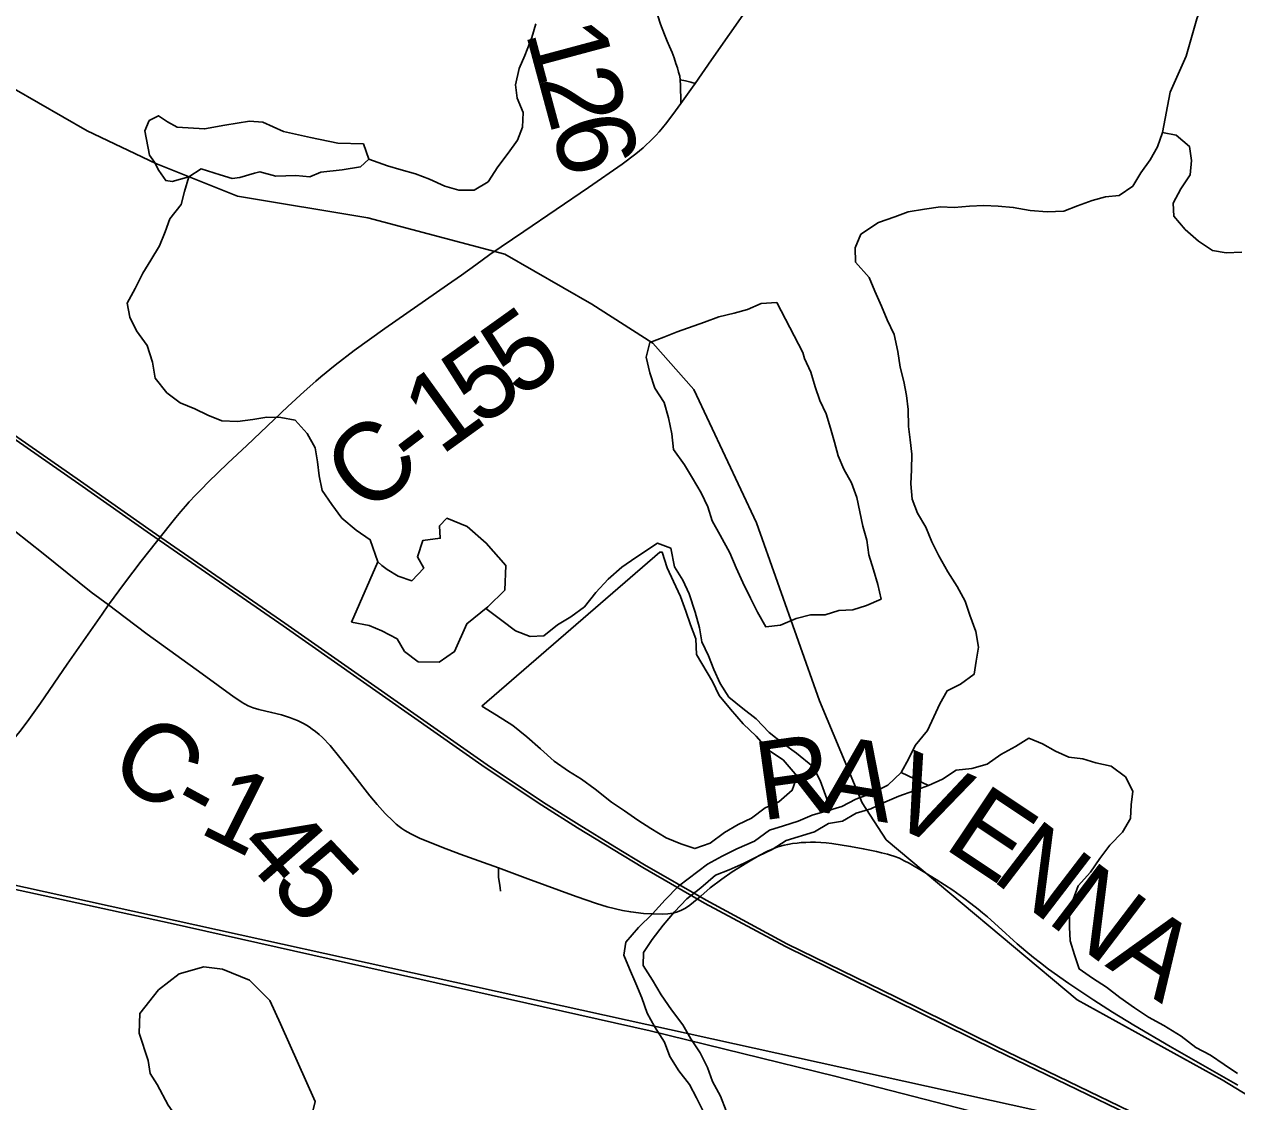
# Model space of a CAD drawing. Extents: x 0 to 34, y 0 to 22.
# Drawn here: x 2.727 to 3.606, y 15.546 to 16.327 of the extents above; entities that cross this region are included whole.
import ezdxf

# ---------------------------------------------------------------- set-up
doc = ezdxf.new("R2010")
doc.units = 0
for name, color, linetype in [('GM_X_County_Road', 7, 'Continuous'), ('GM_X_County_Road_Text', 7, 'Continuous'), ('GM_X_Major_Lake', 7, 'Continuous'), ('GM_X_Major_River', 7, 'Continuous'), ('GM_X_Minor_Lake', 7, 'Continuous'), ('GM_X_Minor_River', 7, 'Continuous'), ('GM_X_Rail_Line', 7, 'Continuous'), ('GM_X_Township_Road', 7, 'Continuous'), ('GM_X_Township_Road_Text', 7, 'Continuous')]:
    doc.layers.add(name, color=color, linetype=linetype)

msp = doc.modelspace()

# ---------------------------------------------------------------- linework, layer by layer
at = {"layer": 'GM_X_County_Road'}
for points in [[(3.21325, 16.2844), (3.22511, 16.30148), (3.25115, 16.33858), (3.26321, 16.35568), (3.28202, 16.38267), (3.2934, 16.39887), (3.29907, 16.407), (3.30365, 16.41331)], [(3.20286, 16.26972), (3.21128, 16.28158), (3.21325, 16.2844)], [(2.93829, 16.0684), (2.9421, 16.07173), (2.95225, 16.07998), (2.96608, 16.0906), (2.98827, 16.10666), (3.03365, 16.13823), (3.04381, 16.14533), (3.0543, 16.15285), (3.06436, 16.16019), (3.08899, 16.17707), (3.13581, 16.20881), (3.16029, 16.2258), (3.17019, 16.23325), (3.17279, 16.23541), (3.17541, 16.2376), (3.17796, 16.23998), (3.18022, 16.24209), (3.1826, 16.24432), (3.185, 16.24689), (3.18722, 16.24927), (3.18963, 16.25219), (3.19273, 16.25593), (3.19905, 16.26435), (3.20286, 16.26972)], [(2.7881, 15.9062), (2.7997, 15.92203), (2.81187, 15.93795), (2.83306, 15.96475), (2.837, 15.9696), (2.8405, 15.97392), (2.84392, 15.97782), (2.84664, 15.98092), (2.85129, 15.98593), (2.85551, 15.99022), (2.86045, 15.99522), (2.87469, 16.00908), (2.88827, 16.02182), (2.91799, 16.05011), (2.92989, 16.06108), (2.93829, 16.0684)], [(2.5626, 16.05258), (2.57121, 16.05117), (2.57823, 16.04978), (2.58483, 16.04827), (2.58905, 16.04721), (2.59256, 16.04611), (2.5963, 16.04484), (2.60016, 16.04353), (2.60388, 16.04202), (2.60805, 16.0403), (2.6124, 16.03832), (2.61713, 16.03607), (2.61994, 16.03456), (2.62308, 16.03283), (2.62784, 16.02998), (2.63141, 16.02762), (2.63558, 16.02488), (2.64168, 16.02054), (2.6476, 16.01612), (2.68054, 15.99068), (2.70942, 15.96809), (2.74069, 15.94354), (2.7756, 15.91558), (2.7881, 15.9062)], [(2.59574, 15.75929), (2.60092, 15.76069), (2.60585, 15.76228), (2.64217, 15.775), (2.68627, 15.78944), (2.6896, 15.79061), (2.69271, 15.79169), (2.69623, 15.79318), (2.69901, 15.79436), (2.70174, 15.7957), (2.70347, 15.79655), (2.7067, 15.79841), (2.70879, 15.79988), (2.71077, 15.80126), (2.71289, 15.80306), (2.71503, 15.80487), (2.71727, 15.80709), (2.71944, 15.80926), (2.72388, 15.81445), (2.72912, 15.82141), (2.73885, 15.83508), (2.75828, 15.8632), (2.78361, 15.89954), (2.7881, 15.9062)], [(2.7881, 15.9062), (2.8001, 15.89713), (2.81604, 15.88512), (2.83693, 15.87004), (2.85604, 15.85618), (2.87916, 15.83933), (2.88256, 15.83709), (2.88494, 15.83553), (2.88673, 15.83458), (2.88941, 15.83316), (2.89295, 15.83175), (2.89716, 15.83046), (2.90628, 15.82833), (2.91348, 15.82655), (2.91993, 15.8245), (2.92249, 15.82346), (2.92505, 15.82243), (2.92944, 15.82029), (2.93153, 15.81904), (2.93363, 15.81779), (2.93582, 15.81621), (2.93809, 15.81457), (2.94074, 15.81222), (2.94314, 15.81009), (2.94865, 15.80428), (2.95583, 15.79574), (2.96504, 15.78408), (2.97753, 15.7678), (2.98271, 15.76155), (2.98862, 15.7551), (2.9944, 15.74936), (2.99653, 15.74733), (2.99867, 15.74563), (3.00065, 15.7441), (3.0028, 15.7427), (3.005, 15.74143), (3.00717, 15.74018), (3.01048, 15.73853), (3.0134, 15.73721), (3.02953, 15.73056), (3.04291, 15.72546), (3.0564, 15.72072), (3.07061, 15.71555)], [(3.07061, 15.71555), (3.09202, 15.70775), (3.127, 15.69481), (3.14175, 15.68975), (3.14952, 15.68743), (3.16063, 15.68481), (3.16648, 15.68363), (3.17584, 15.68249), (3.18922, 15.68208), (3.19345, 15.6824), (3.19728, 15.68284), (3.20041, 15.68363), (3.20339, 15.68484), (3.20618, 15.68642), (3.20927, 15.68865), (3.21737, 15.69514), (3.22402, 15.70106), (3.23249, 15.70732), (3.2401, 15.71262), (3.25057, 15.71926), (3.25963, 15.72459), (3.26566, 15.72767), (3.27301, 15.73079), (3.27772, 15.73206), (3.28028, 15.73256), (3.28374, 15.73322), (3.28706, 15.7336), (3.28988, 15.73393), (3.29326, 15.73407), (3.29671, 15.73422), (3.30036, 15.73413), (3.30421, 15.73403), (3.30811, 15.73369), (3.31231, 15.73331), (3.32578, 15.73115), (3.33495, 15.72947), (3.34466, 15.72745), (3.34826, 15.72659), (3.35247, 15.72559), (3.35477, 15.72489), (3.35715, 15.72416), (3.36112, 15.7226), (3.36461, 15.72081), (3.36824, 15.71894), (3.3784, 15.71305), (3.38789, 15.70713), (3.39986, 15.69935), (3.40795, 15.69364), (3.41298, 15.68976), (3.41823, 15.68572), (3.42148, 15.68302), (3.42489, 15.68018), (3.43271, 15.67313), (3.44654, 15.66065), (3.45287, 15.6553), (3.4584, 15.6506), (3.46334, 15.64683), (3.46928, 15.64229), (3.48392, 15.63175), (3.50203, 15.61966), (3.51566, 15.61093), (3.53107, 15.60155), (3.55728, 15.586), (3.60646, 15.55803)]]:
    msp.add_lwpolyline(points, dxfattribs=at)
at = {"layer": 'GM_X_Major_Lake'}
msp.add_line((3.36247, 15.78464), (3.38221, 15.77531), dxfattribs=at)
msp.add_line((3.36247, 15.78464), (3.38221, 15.77531), dxfattribs=at)
for points in [[(3.60931, 16.16196), (3.59796, 16.16149), (3.5881, 16.16331), (3.57783, 16.17006), (3.5683, 16.17832), (3.5599, 16.18812), (3.55945, 16.19759), (3.56504, 16.20787), (3.57177, 16.21817), (3.57283, 16.22841), (3.57124, 16.23864), (3.56171, 16.24691), (3.55185, 16.24872), (3.54815, 16.23846), (3.54293, 16.22894), (3.53619, 16.21941), (3.53021, 16.20988), (3.52042, 16.20298), (3.51059, 16.20214), (3.50077, 16.19941), (3.4902, 16.19554), (3.48039, 16.19167), (3.46828, 16.1912), (3.45579, 16.19224), (3.44366, 16.19442), (3.43267, 16.19547), (3.42245, 16.19577), (3.41186, 16.19531), (3.40089, 16.19447), (3.39105, 16.19477), (3.37933, 16.19316), (3.36761, 16.19118), (3.3578, 16.18769), (3.3461, 16.18343), (3.3333, 16.17499), (3.32921, 16.1651), (3.32929, 16.15486), (3.33922, 16.14356), (3.34346, 16.13373), (3.34809, 16.12278), (3.35233, 16.11295), (3.35733, 16.10237), (3.36008, 16.08988), (3.36168, 16.07851), (3.36441, 16.0683), (3.36638, 16.05807), (3.3676, 16.04785), (3.36769, 16.03571), (3.3689, 16.02586), (3.37012, 16.01564), (3.36983, 16.00426), (3.36953, 15.99402), (3.37038, 15.98303), (3.37424, 15.97282), (3.38038, 15.96263), (3.38462, 15.95204), (3.38962, 15.94184), (3.39615, 15.93014), (3.40305, 15.91957), (3.40881, 15.909), (3.41229, 15.89879), (3.41655, 15.88707), (3.41853, 15.87571), (3.41672, 15.86545), (3.41528, 15.85596), (3.40549, 15.84868), (3.39569, 15.84406), (3.39047, 15.83454), (3.386, 15.82502), (3.38154, 15.81513), (3.37254, 15.80444), (3.36807, 15.79493), (3.36247, 15.78464)], [(3.38221, 15.77531), (3.39241, 15.77995), (3.4022, 15.78647), (3.41354, 15.78769), (3.42487, 15.79082), (3.43466, 15.79772), (3.44521, 15.80349), (3.455, 15.80963), (3.46487, 15.80553), (3.47438, 15.8003), (3.48387, 15.79582), (3.4941, 15.79476), (3.50359, 15.7918)], [(3.50359, 15.7918), (3.51458, 15.78923), (3.52486, 15.78173), (3.53024, 15.77115), (3.52919, 15.76129), (3.52851, 15.75142), (3.5229, 15.74152), (3.51352, 15.73197), (3.5064, 15.72243), (3.49967, 15.71252), (3.49066, 15.70259), (3.48695, 15.6927), (3.48439, 15.68244), (3.48446, 15.67258), (3.48492, 15.66273), (3.48802, 15.65251), (3.49151, 15.6423), (3.50103, 15.63555), (3.5113, 15.62918), (3.52082, 15.62167), (3.53147, 15.61417), (3.54174, 15.60742), (3.55277, 15.60144), (3.56532, 15.59357), (3.57598, 15.58532), (3.58662, 15.57971), (3.59651, 15.57296), (3.60602, 15.56659)]]:
    msp.add_lwpolyline(points, dxfattribs=at)
at = {"layer": 'GM_X_Major_River'}
msp.add_line((3.38221, 15.77531), (3.36247, 15.78464), dxfattribs=at)
msp.add_line((3.38221, 15.77531), (3.36247, 15.78464), dxfattribs=at)
for points in [[(3.36247, 15.78464), (3.3527, 15.77547)], [(3.3527, 15.77547), (3.3414, 15.76969), (3.32969, 15.76543), (3.31952, 15.76004), (3.30894, 15.75693), (3.29799, 15.75381), (3.28781, 15.74956), (3.27724, 15.74607), (3.26705, 15.74296), (3.25613, 15.73491), (3.2433, 15.7295), (3.23275, 15.72411), (3.2222, 15.71834), (3.20113, 15.70225), (3.19137, 15.69232), (3.18236, 15.68239), (3.17222, 15.67245), (3.16284, 15.66176), (3.1614, 15.65227), (3.16564, 15.64244), (3.17027, 15.63186), (3.17451, 15.62127), (3.17838, 15.61031), (3.18376, 15.60049), (3.19104, 15.58917), (3.1949, 15.57896), (3.20142, 15.56839), (3.20907, 15.55859), (3.21406, 15.54877), (3.21983, 15.53782)], [(3.23571, 15.53946), (3.23146, 15.55004), (3.2257, 15.56061), (3.22222, 15.57083), (3.21684, 15.5814), (3.20994, 15.59159), (3.20419, 15.60178), (3.19615, 15.61272), (3.1885, 15.62365), (3.18236, 15.63423), (3.17547, 15.64479), (3.17577, 15.65427), (3.18213, 15.6638), (3.19, 15.6741), (3.19825, 15.68365), (3.20726, 15.6932), (3.21741, 15.70124), (3.22794, 15.71042), (3.23775, 15.71429), (3.24869, 15.71892), (3.25924, 15.72431), (3.26905, 15.72894), (3.27921, 15.73546), (3.2996, 15.74169), (3.30977, 15.74783), (3.31998, 15.74943), (3.32978, 15.75519), (3.34035, 15.75831), (3.35053, 15.76332), (3.36071, 15.76757), (3.37166, 15.77144), (3.38221, 15.77531)]]:
    msp.add_lwpolyline(points, dxfattribs=at)
at = {"layer": 'GM_X_Minor_Lake'}
for p, q in [((2.89769, 16.22015), (2.90945, 16.21721)), ((3.2912, 16.08935), (3.27237, 16.1256)), ((2.98318, 15.93757), (2.96422, 15.89381)), ((3.1875, 15.94445), (3.05856, 15.83273)), ((2.81842, 15.56658), (2.8234, 15.55865))]:
    msp.add_line(p, q, dxfattribs=at)
for points in [[(2.90945, 16.21721), (2.92383, 16.2177), (2.93405, 16.21664), (2.94197, 16.22012), (2.95748, 16.22175), (2.97071, 16.22375), (2.97672, 16.22949), (2.97285, 16.24045), (2.9543, 16.24107), (2.93459, 16.24509), (2.91487, 16.24948), (2.90006, 16.2562), (2.89021, 16.25688), (2.87244, 16.25409), (2.85771, 16.25132), (2.83801, 16.25268), (2.8308, 16.25642), (2.82432, 16.26092), (2.81754, 16.25745), (2.81457, 16.24985), (2.81774, 16.23243), (2.82156, 16.22715), (2.82464, 16.22111), (2.82962, 16.21394), (2.83416, 16.21322), (2.84625, 16.21672), (2.85528, 16.22248), (2.86894, 16.21804), (2.87767, 16.21545), (2.88334, 16.21625), (2.89391, 16.21937), (2.89769, 16.22015)], [(3.27237, 16.1256), (3.26102, 16.12476), (3.25121, 16.12051), (3.2414, 16.11778), (3.23044, 16.11504), (3.21987, 16.11117), (3.20025, 16.10419), (3.19044, 16.10032), (3.18025, 16.09645), (3.17768, 16.08581), (3.18042, 16.07446), (3.18391, 16.06349), (3.19081, 16.05293), (3.19392, 16.04195), (3.19629, 16.03022), (3.19751, 16.01885), (3.20555, 16.00792), (3.2113, 15.9981), (3.21744, 15.98753), (3.22244, 15.97733), (3.22555, 15.96712), (3.2313, 15.95693), (3.23822, 15.94408), (3.24284, 15.93312), (3.24785, 15.92254), (3.25323, 15.91121), (3.25824, 15.90101), (3.26437, 15.89044), (3.27496, 15.89166), (3.28628, 15.8963), (3.29686, 15.89904), (3.30745, 15.89912), (3.31727, 15.90222), (3.32748, 15.90268), (3.3373, 15.90579), (3.34786, 15.91043), (3.34551, 15.92102), (3.3424, 15.93162), (3.3389, 15.94259), (3.33768, 15.9532), (3.33458, 15.96341), (3.3326, 15.97363), (3.33025, 15.98423), (3.32638, 15.99482), (3.32101, 16.00464), (3.31676, 16.01446), (3.31404, 16.0243), (3.31131, 16.03452), (3.3082, 16.04473), (3.30358, 16.05455), (3.3001, 16.06439), (3.29699, 16.07498), (3.29237, 16.0848), (3.2912, 16.08935)], [(2.96422, 15.89381), (2.9771, 15.89126), (2.98622, 15.88754), (2.99724, 15.88155), (3.00261, 15.8725), (3.01251, 15.86499), (3.02765, 15.86473), (3.03894, 15.8724), (3.04787, 15.89256), (3.06291, 15.90481), (3.07531, 15.91704), (3.07592, 15.93487), (3.06179, 15.95107), (3.04807, 15.96309), (3.03326, 15.96905), (3.02801, 15.9637), (3.02846, 15.9546), (3.01598, 15.95299), (3.01191, 15.9412), (3.01652, 15.93289), (3.00788, 15.92373), (2.99802, 15.92706), (2.99003, 15.93193), (2.98622, 15.93493), (2.98318, 15.93757)], [(3.05856, 15.83273), (3.06921, 15.82637), (3.081, 15.81887), (3.09128, 15.81061), (3.10119, 15.80197), (3.1111, 15.79294), (3.12137, 15.78582), (3.13088, 15.77982), (3.14078, 15.7727), (3.15258, 15.76331), (3.1621, 15.75693), (3.17161, 15.75018), (3.18112, 15.74419), (3.19215, 15.73745), (3.20278, 15.73298), (3.21303, 15.72965), (3.22397, 15.73352), (3.23451, 15.74119), (3.2443, 15.74695), (3.25411, 15.75157), (3.26389, 15.75923), (3.2737, 15.76348), (3.28347, 15.7719), (3.28718, 15.78217), (3.27687, 15.79384), (3.26621, 15.80097), (3.25743, 15.81114), (3.24789, 15.82016), (3.23873, 15.83071), (3.2307, 15.84051), (3.2257, 15.85071), (3.21419, 15.87034), (3.21373, 15.88171), (3.20986, 15.89192), (3.20638, 15.90175), (3.20251, 15.91234), (3.1975, 15.92329), (3.19289, 15.93312), (3.18939, 15.94447), (3.1875, 15.94445)], [(2.8234, 15.55865), (2.83147, 15.54355), (2.8418, 15.52884), (2.85248, 15.51792), (2.86734, 15.50552), (2.87984, 15.5041), (2.8991, 15.51032), (2.91538, 15.50893), (2.9312, 15.51891), (2.9378, 15.54626), (2.91276, 15.60257), (2.90505, 15.61957), (2.89018, 15.63425), (2.87081, 15.64207), (2.85718, 15.64386), (2.83943, 15.63879), (2.82438, 15.6273), (2.81089, 15.61013), (2.81024, 15.59572), (2.81683, 15.57604), (2.81842, 15.56658)]]:
    msp.add_lwpolyline(points, dxfattribs=at)
at = {"layer": 'GM_X_Minor_River'}
for points in [[(3.55185, 16.24872), (3.5573, 16.27797), (3.56883, 16.30422), (3.57657, 16.3312), (3.58954, 16.36619), (3.59464, 16.39163), (3.59412, 16.40869), (3.59174, 16.42308), (3.59202, 16.4356)], [(2.97672, 16.22949), (2.99038, 16.22466), (3.00025, 16.2217), (3.01049, 16.21875), (3.02074, 16.21504), (3.03175, 16.20981), (3.042, 16.20686), (3.05297, 16.20695), (3.06314, 16.21309), (3.07025, 16.22376), (3.07774, 16.23368), (3.08448, 16.24321), (3.08819, 16.25272), (3.08848, 16.26334), (3.08424, 16.27354), (3.08303, 16.28339), (3.08558, 16.29517), (3.08967, 16.30468), (3.09487, 16.31761), (3.09782, 16.32749)], [(2.98318, 15.93757), (2.97775, 15.95345), (2.96748, 15.96057), (2.95719, 15.96922), (2.94992, 15.97902), (2.94303, 15.9892), (2.94068, 15.9998), (2.93946, 16.01003), (2.93787, 16.02026), (2.93211, 16.03045), (2.92333, 16.04024), (2.91309, 16.04206), (2.90287, 16.04236), (2.89267, 16.04076), (2.8817, 16.03916), (2.87034, 16.03983), (2.86009, 16.04393), (2.8506, 16.0484), (2.83996, 16.05287), (2.83044, 16.06), (2.82204, 16.07055), (2.82005, 16.08229), (2.81617, 16.0944), (2.80852, 16.10496), (2.80352, 16.11478), (2.80155, 16.125), (2.80752, 16.13566), (2.81311, 16.1467), (2.81871, 16.15622), (2.82507, 16.16651), (2.82915, 16.17678), (2.83248, 16.18628), (2.84073, 16.19658), (2.8433, 16.20608), (2.84625, 16.21672)], [(3.31148, 15.75768), (3.30772, 15.7683), (3.30385, 15.77888), (3.29847, 15.78908), (3.28666, 15.79885), (3.27715, 15.8056), (3.26687, 15.81386), (3.25733, 15.82365), (3.24781, 15.83116), (3.23752, 15.83942), (3.23139, 15.84923), (3.22677, 15.85944), (3.22291, 15.86927), (3.21791, 15.87947), (3.21631, 15.88969), (3.2132, 15.90104), (3.20893, 15.91428), (3.20431, 15.92411), (3.19818, 15.93392), (3.19553, 15.9474), (3.1858, 15.951), (3.17012, 15.94053), (3.15995, 15.93362), (3.15018, 15.92482), (3.14118, 15.91528), (3.13293, 15.90497), (3.12315, 15.89769), (3.11335, 15.89193), (3.10357, 15.88389), (3.09374, 15.88344), (3.08311, 15.88753), (3.07321, 15.89503), (3.06152, 15.90368)]]:
    msp.add_lwpolyline(points, dxfattribs=at)
at = {"layer": 'GM_X_Rail_Line'}
for points in [[(2.11404, 16.8374), (2.11458, 16.83676), (2.1893, 16.75144), (2.2758, 16.63594), (2.32038, 16.58606), (2.38068, 16.52962), (2.50392, 16.43116), (2.61143, 16.35633), (2.70189, 16.29068), (2.7727, 16.24998), (2.82252, 16.22634), (2.88153, 16.2027), (2.97595, 16.18691), (3.07524, 16.16059), (3.13833, 16.12429), (3.18262, 16.09607), (3.21214, 16.06247), (3.25775, 15.96574), (3.30335, 15.83677), (3.3342, 15.76288), (3.35164, 15.736), (3.48992, 15.62004), (3.59498, 15.56194), (3.68719, 15.50564)], [(3.62937, 15.49013), (3.53553, 15.53548), (3.43164, 15.58576), (3.35923, 15.62155), (3.27967, 15.66062), (3.22117, 15.69212), (3.17637, 15.71789), (3.15489, 15.73098), (3.12912, 15.74673), (3.10335, 15.7631), (3.06244, 15.7903), (2.91598, 15.89299), (2.81985, 15.95946), (2.76789, 15.99587), (2.7008, 16.04271), (2.59761, 16.11492), (2.4486, 16.21924), (2.34939, 16.28837), (2.27299, 16.34186), (2.18995, 16.39965), (2.11404, 16.45303)], [(3.62833, 15.48803), (3.5345, 15.53338), (3.43061, 15.58366), (3.3582, 15.61946), (3.27859, 15.65855), (3.22002, 15.69008), (3.17517, 15.71589), (3.15367, 15.72899), (3.12788, 15.74476), (3.10207, 15.76114), (3.06111, 15.78838), (2.91464, 15.89107), (2.8185, 15.95755), (2.76655, 15.99396), (2.69946, 16.0408), (2.59626, 16.11301), (2.44725, 16.21733), (2.34805, 16.28646), (2.27165, 16.33995), (2.1886, 16.39774), (2.11404, 16.45017)], [(2.11404, 15.83803), (2.21072, 15.81673), (2.40039, 15.77358), (3.45866, 15.54025), (3.56111, 15.51059), (3.62916, 15.49068)], [(3.91685, 15.34723), (3.85553, 15.37214), (3.6811, 15.44955), (3.57506, 15.49641), (3.50847, 15.51449), (3.31447, 15.56464), (3.18048, 15.59752), (2.83277, 15.67561), (2.27379, 15.79727), (2.13158, 15.82604)]]:
    msp.add_lwpolyline(points, dxfattribs=at)
at = {"layer": 'GM_X_Township_Road'}
for points in [[(3.20235, 16.28697), (3.20198, 16.28956), (3.20119, 16.2924), (3.20035, 16.29564), (3.1993, 16.29886), (3.19795, 16.30285), (3.19651, 16.30679), (3.19459, 16.31112), (3.19296, 16.31486), (3.19103, 16.31979), (3.1881, 16.3273), (3.18453, 16.33855), (3.1804, 16.35288), (3.17722, 16.36548), (3.17635, 16.36982), (3.17548, 16.37415), (3.17461, 16.37982), (3.17372, 16.3857), (3.17279, 16.39466), (3.17109, 16.40992), (3.17066, 16.41377)], [(3.20286, 16.26972), (3.20271, 16.27344), (3.20259, 16.28031), (3.20247, 16.2829), (3.20235, 16.28697)], [(3.21325, 16.2844), (3.20997, 16.2852), (3.2063, 16.28611), (3.20235, 16.28697)], [(3.07226, 15.69869), (3.07196, 15.70115), (3.07145, 15.70446), (3.07075, 15.70873), (3.07061, 15.71064), (3.07061, 15.7126), (3.07061, 15.71555)]]:
    msp.add_lwpolyline(points, dxfattribs=at)

# ---------------------------------------------------------------- texts
at = {"layer": 'GM_X_County_Road_Text'}
for s, rotation, p in [('5', 35.61148, (3.08567, 16.05483)), ('5', 35.64475, (3.05724, 16.03444)), ('1', 35.84257, (3.02891, 16.01397)), ('C', 41.34086, (2.97641, 15.96994)), ('-', 37.19307, (3.01061, 16.00008)), ('C', 323.76631, (2.78552, 15.78596)), ('R', 7.88558, (3.26114, 15.74982)), ('A', 350.77663, (3.3029, 15.75627)), ('V', 336.56273, (3.34868, 15.7493)), ('1', 333.30751, (2.85244, 15.7418)), ('-', 331.3258, (2.83007, 15.75399)), ('E', 326.28498, (3.39219, 15.7307)), ('4', 311.42826, (2.8792, 15.72955)), ('N', 322.5589, (3.42675, 15.70768)), ('5', 313.36696, (2.90377, 15.70176)), ('N', 322.77981, (3.46664, 15.67714)), ('A', 326.28146, (3.50954, 15.6447))]:
    msp.add_text(s, height=0.05682, rotation=rotation, dxfattribs=at).set_placement(p)
at = {"layer": 'GM_X_Township_Road_Text'}
for s, rotation, p in [('1', 285.03251, (3.0901, 16.32147)), ('2', 285.1072, (3.09913, 16.28786)), ('6', 285.10987, (3.10818, 16.25433))]:
    msp.add_text(s, height=0.05682, rotation=rotation, dxfattribs=at).set_placement(p)

doc.saveas('drawing.dxf')
